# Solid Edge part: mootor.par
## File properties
Author: Mac
Template: Normal.par
Last saved by: Mac
Revision: 3
Application: Solid Edge
Material: Iron
Face Style: Grey
Fill Style: ANSI31(Iron)
Virtual Style: Iron coarse
Coef. of Thermal Exp: 1.1e-05
Thermal Conductivity: 48.0
Specific Heat: 544.0
Modulus of Elasticity: 66190000000.0
Poission's Ratio: 0.29
Yield Stress: 572264831.0
Ultimate Stress: 137895140.0
Elongation: 0.0
Density: 6920,000 kg/m^3
Accuracy: 0,990
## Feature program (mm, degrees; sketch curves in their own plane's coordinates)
sketch for "unnamed Protrusion 1" plane through (0, 0, 0) normal (1, 0, 0) x-axis (0, 1, 0)
  line (-7, 0) -> (-7, 14)
  line (-7, 14) -> (7, 14)
  line (7, 14) -> (7, 0)
  line (7, 0) -> (-7, 0)
  dimension (linear) = 7
extrude "unnamed Protrusion 1" add finite 16 along -normal
sketch for "ExtrudedProtrusion_2" plane through (-8, 0, 0) normal (0, 0, -1) x-axis (0, 1, 0)
extrude "ExtrudedProtrusion_2" add finite 2 along +normal
sketch for "ExtrudedCutout_1" #1 plane through (-8, 5.5, -2) normal (0, 0, -1) x-axis (0, -1, 0)
  line (-0.9, 2) -> (1.5, 2)
  line (1.5, 2) -> (1.5, -2)
  line (1.5, -2) -> (-0.9, -2)
  line (-0.9, -2) -> (-0.9, 2)
sketch for "ExtrudedCutout_1" #2 plane through (-8, 5.5, -2) normal (0, 0, -1) x-axis (0, -1, 0)
  line (-2.7324, 8.6089) -> (2.1, 8.6089)
  line (2.1, 8.6089) -> (2.1, -8.8485)
  line (2.1, -8.8485) -> (-2.7324, -8.8485)
  line (-2.7324, -8.8485) -> (-2.7324, 8.6089)
sketch for "ExtrudedCutout_1" #3 plane through (-8, 5.5, -2) normal (0, 0, -1) x-axis (0, -1, 0)
  line (11.9, 2) -> (9.5, 2)
  line (9.5, 2) -> (9.5, -2)
  line (9.5, -2) -> (11.9, -2)
  line (11.9, -2) -> (11.9, 2)
sketch for "ExtrudedCutout_1" #4 plane through (-8, 5.5, -2) normal (0, 0, -1) x-axis (0, -1, 0)
extrude "ExtrudedCutout_1" cut finite 3 along -normal
fillet "Round_1" radius 0.5
sketch for "ExtrudedCutout_2" #1 plane through (-8, 5.2, 1) normal (0, 0, -1) x-axis (0, -1, 0)
  circle centre (0, 0) radius 0.2
sketch for "ExtrudedCutout_2" #2 plane through (-8, 5.2, 1) normal (0, 0, -1) x-axis (0, -1, 0)
  line (1.8, 8) -> (1.8, -8)
  line (1.8, -8) -> (-1.8, -8)
  line (-1.8, -8) -> (-1.8, 8)
  line (1.8, 8) -> (-1.8, 8)
sketch for "ExtrudedCutout_2" #3 plane through (-8, 5.2, 1) normal (0, 0, -1) x-axis (0, -1, 0)
  circle centre (10.4, 0) radius 0.2
sketch for "ExtrudedCutout_2" #4 plane through (-8, 5.2, 1) normal (0, 0, -1) x-axis (0, -1, 0)
  line (8.6, 8) -> (8.6, -8)
  line (8.6, -8) -> (12.2, -8)
  line (12.2, -8) -> (12.2, 8)
  line (8.6, 8) -> (12.2, 8)
extrude "ExtrudedCutout_2" cut finite 0.6 along -normal
sketch for "unnamed Cutout 1" #1 plane through (-16, 0, 6) normal (-1, 0, 0) x-axis (0, -1, 0)
  line (-7, 8) -> (-7, -4.4)
  line (-7, -4.4) -> (-5.6, -4.4)
  line (-5.6, -4.4) -> (-5.6, -3.9)
  line (-5.6, -3.9) -> (-4.2, -3.4)
  line (-4.2, -3.4) -> (-3.2429, -3.4)
  arc centre (0, -4.4328) radius 3.4034 from (-3.2429, -3.4) to (-2.5, -2.1234) cw
  line (-2.5, 3) -> (-2.5, -2.1234)
  line (-2.5, 3) -> (-2.4, 3)
  line (-2.4, 3) -> (-2.4, 7.69)
  arc centre (-2.1, 7.69) radius 0.3 from (-2.1, 7.99) to (-2.4, 7.69) ccw
  line (-2.1, 7.99) -> (2.1, 7.99)
  arc centre (2.1, 7.69) radius 0.3 from (2.1, 7.99) to (2.4, 7.69) cw
  line (2.4, 3) -> (2.4, 7.69)
  line (2.4, 3) -> (2.5, 3)
  line (2.5, 3) -> (2.5, -2.1234)
  arc centre (0, -4.4328) radius 3.4034 from (2.5, -2.1234) to (3.2429, -3.4) cw
  line (3.2429, -3.4) -> (4.2, -3.4)
  line (5.6, -3.9) -> (4.2, -3.4)
  line (5.6, -4.4) -> (5.6, -3.9)
  line (7, -4.4) -> (5.6, -4.4)
  line (7, -4.4) -> (7, 8)
  line (7, 8) -> (-7, 8)
sketch for "unnamed Cutout 1" #2 plane through (-16, 0, 6) normal (-1, 0, 0) x-axis (0, -1, 0)
  line (0, -8) -> (-3.4, -6.7625)
  line (-3.4, -6.7625) -> (-4.6491, -6.7625)
  line (-4.6491, -6.7625) -> (-4.6491, -8.8314)
  line (-4.6491, -8.8314) -> (4.6864, -8.8314)
  line (4.6864, -8.8314) -> (4.6864, -6.7625)
  line (4.6864, -6.7625) -> (3.4, -6.7625)
  line (0, -8) -> (3.4, -6.7625)
extrude "unnamed Cutout 1" cut through along -normal
fillet "Round_2" radius 0.2
sketch for "unnamed Cutout 2" #1 plane through (-8, 5.8143, 1.6) normal (0, 0, -1) x-axis (0, -1, 0)
  line (-2.111, -0.3239) -> (2.4143, -1.971)
  line (2.4143, -1.971) -> (2.4143, -8.835)
  line (2.4143, -8.835) -> (-2.4143, -8.835)
  line (-2.4143, -8.835) -> (-2.4143, 8.835)
  line (-2.4143, 8.835) -> (2.4143, 8.835)
  line (2.4143, 8.835) -> (2.4143, 2)
  line (2.4143, 2) -> (-2.111, 0.3529)
  line (-2.111, 0.3529) -> (-2.111, -0.3239)
sketch for "unnamed Cutout 2" #2 plane through (-8, 5.8143, 1.6) normal (0, 0, -1) x-axis (0, -1, 0)
  line (9.0775, 8.835) -> (9.0775, 2)
  line (9.0775, 2) -> (13.6028, 0.3529)
  line (13.6028, 0.3529) -> (13.6028, -0.3239)
  line (13.6028, -0.3239) -> (9.0775, -1.971)
  line (9.0775, -1.971) -> (9.0775, -8.835)
  line (9.0775, -8.835) -> (13.906, -8.835)
  line (13.906, -8.835) -> (13.906, 8.835)
  line (13.906, 8.835) -> (9.0775, 8.835)
extrude "unnamed Cutout 2" cut to key point along -normal
sketch for "ExtrudedProtrusion_4" plane through (-16, 0, 6.1014) normal (-1, 0, 0) x-axis (0, -1, 0)
  circle centre (0, -4.5342) radius 2.7256
extrude "ExtrudedProtrusion_4" add finite 0.4 along +normal
sketch for "ExtrudedCutout_5" #1 plane through (-16.4, 0, 1.5672) normal (-1, 0, 0) x-axis (0, -1, 0)
  circle centre (0, 0) radius 2.4942
sketch for "ExtrudedCutout_5" #2 plane through (-16.4, 0, 1.5672) normal (-1, 0, 0) x-axis (0, -1, 0)
  circle centre (0, 0) radius 1.2811
extrude "ExtrudedCutout_5" cut finite 0.2 along -normal
fillet "Round_4" radius 0.1
sketch for "ExtrudedCutout_6" plane through (-16, 0, 6.1014) normal (-1, 0, 0) x-axis (0, -1, 0)
  circle centre (-0.0184, 4.9894) radius 0.25
extrude "ExtrudedCutout_6" cut finite 0.1 along -normal
fillet "Round_6" radius 0.1
sketch for "unnamed Cutout 3" #1 plane through (-8, 0, 13.99) normal (0, 0, 1) x-axis (0, -1, 0)
  line (-4.853, -7.9) -> (5.6008, -7.9)
  line (5.6008, -7.9) -> (5.6008, -10.3024)
  line (5.6008, -10.3024) -> (-4.853, -10.3024)
  line (-4.853, -10.3024) -> (-4.853, -7.9)
sketch for "unnamed Cutout 3" #2 plane through (-8, 0, 13.99) normal (0, 0, 1) x-axis (0, -1, 0)
  line (-4.853, 7.9) -> (7.6298, 7.9)
  line (7.6298, 9.7384) -> (7.6298, 7.9)
  line (-4.853, 9.7384) -> (7.6298, 9.7384)
  line (-4.853, 7.9) -> (-4.853, 9.7384)
extrude "unnamed Cutout 3" cut to key point along -normal
fillet "Round_7" radius 0.3
sketch for "ExtrudedProtrusion_5" #1 plane through (-8, 0, 13.99) normal (0, 0, 1) x-axis (1, 0, 0)
  line (-7.3209, 1.7743) -> (7.1717, 1.7743)
  line (7.1717, 1.7743) -> (7.1717, 1.655)
  line (7.1717, 1.655) -> (-7.3209, 1.655)
  line (-7.3209, 1.655) -> (-7.3209, 1.7743)
sketch for "ExtrudedProtrusion_5" #11 plane through (-8, 0, 13.99) normal (0, 0, 1) x-axis (1, 0, 0)
  line (0.7306, 1.0586) -> (7.1717, 1.0586)
  line (7.1717, 1.0586) -> (7.1717, 0.9393)
  line (7.1717, 0.9393) -> (0.7306, 0.9393)
  line (0.7306, 0.9393) -> (0.7306, 1.0586)
sketch for "ExtrudedProtrusion_5" #12 plane through (-8, 0, 13.99) normal (0, 0, 1) x-axis (1, 0, 0)
  line (0.7902, 0.3728) -> (7.1717, 0.3728)
  line (7.1717, 0.3728) -> (7.1717, 0.2237)
  line (7.1717, 0.2237) -> (0.7902, 0.2237)
  line (0.7902, 0.2237) -> (0.7902, 0.3728)
sketch for "ExtrudedProtrusion_5" #13 plane through (-8, 0, 13.99) normal (0, 0, 1) x-axis (1, 0, 0)
  line (-7.3209, -1.7743) -> (7.1717, -1.7743)
  line (7.1717, -1.7743) -> (7.1717, -1.655)
  line (7.1717, -1.655) -> (-7.3209, -1.655)
  line (-7.3209, -1.655) -> (-7.3209, -1.7743)
sketch for "ExtrudedProtrusion_5" #14 plane through (-8, 0, 13.99) normal (0, 0, 1) x-axis (1, 0, 0)
  line (0.7306, -1.0586) -> (7.1717, -1.0586)
  line (7.1717, -1.0586) -> (7.1717, -0.9393)
  line (7.1717, -0.9393) -> (0.7306, -0.9393)
  line (0.7306, -0.9393) -> (0.7306, -1.0586)
sketch for "ExtrudedProtrusion_5" #15 plane through (-8, 0, 13.99) normal (0, 0, 1) x-axis (1, 0, 0)
  line (0.7902, -0.3728) -> (7.1717, -0.3728)
  line (7.1717, -0.3728) -> (7.1717, -0.2237)
  line (7.1717, -0.2237) -> (0.7902, -0.2237)
  line (0.7902, -0.2237) -> (0.7902, -0.3728)
sketch for "ExtrudedProtrusion_5" #16 plane through (-8, 0, 13.99) normal (0, 0, 1) x-axis (1, 0, 0)
  line (-7.1419, 1.2674) -> (0.446, 1.2674)
  line (0.446, 1.2674) -> (0.446, -0.999)
  line (0.446, -0.999) -> (-7.1419, -0.999)
  line (-7.1419, -0.999) -> (-7.1419, 1.2674)
sketch for "ExtrudedProtrusion_5" #17 plane through (-8, 0, 13.99) normal (0, 0, 1) x-axis (1, 0, 0)
  line (-6.963, 1.0586) -> (0.2535, 1.0586)
  line (0.2535, 1.0586) -> (0.2535, -0.7604)
  line (0.2535, -0.7604) -> (-6.963, -0.7604)
  line (-6.963, -0.7604) -> (-6.963, 1.0586)
extrude "ExtrudedProtrusion_5" add finite 0.05 along +normal
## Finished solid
Body 1: solid body, 235 faces, 573 edges, 354 vertices.
  Faces by surface: plane 137, cylinder 38, swept 38, blend 8, torus 8, sphere 6
  Edges by curve: line 307, spline 162, circle 78, ellipse 16, intersection 10
Bounding box of the edges (mm; curved faces can reach further): 16.400 x 12.800 x 16.027, from (-16.4, -6.4, -1.9872) to (0, 6.4, 14.04).
Cylindrical faces by radius (mm): R0.1 x10, R0.2 x9, R0.3 x8, R0.5 x8, R2.7256 x1, R3.4034 x2
Toroidal faces (ring radius, tube radius in mm): R1.1811 r0.1 x1, R1.3811 r0.1 x1, R2.3942 r0.1 x1, R2.5942 r0.1 x1, R3.3034 r0.1 x4
Spherical faces by radius (mm): R0.2 x2, R0.3 x4
Planar faces by outward normal: +x 18, +y 14, +z 25, -x 21, -y 19, -z 4, oblique 36
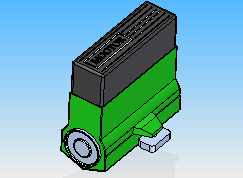
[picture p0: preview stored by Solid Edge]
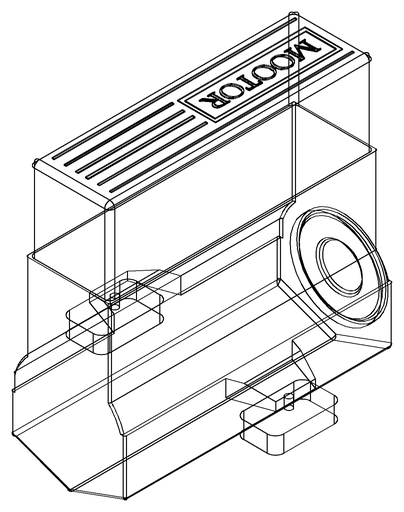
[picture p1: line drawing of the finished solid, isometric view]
